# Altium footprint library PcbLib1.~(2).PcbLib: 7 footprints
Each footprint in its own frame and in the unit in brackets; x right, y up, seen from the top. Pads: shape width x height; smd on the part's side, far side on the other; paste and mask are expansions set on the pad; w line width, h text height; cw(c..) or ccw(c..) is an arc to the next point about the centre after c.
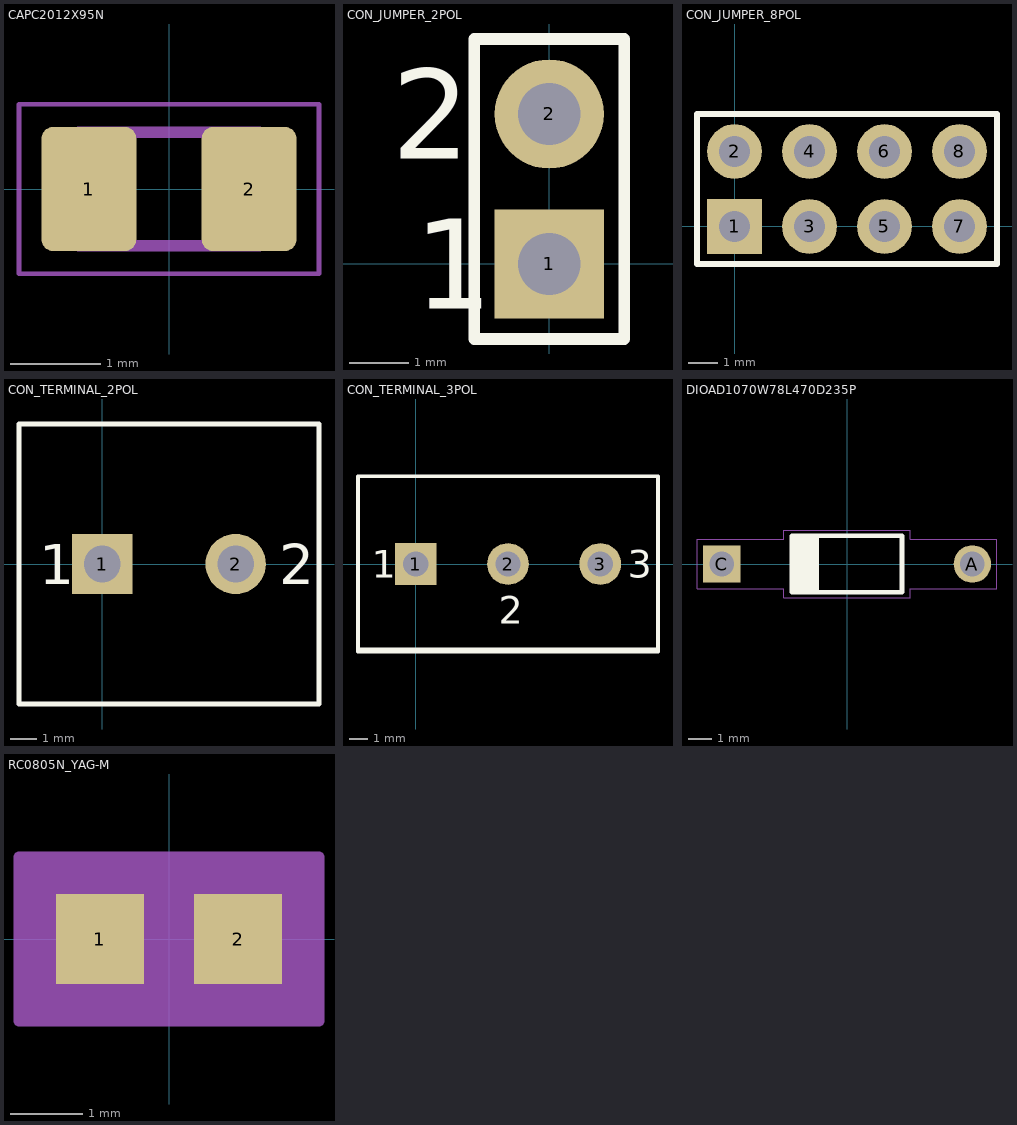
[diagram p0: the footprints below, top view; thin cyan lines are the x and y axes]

## CAPC2012X95N [mm]
pads (2):
  rrect25% 1.05x1.38 smd: 1(-0.888,0) 2(0.888,0)
Mechanical 13:
  lines w0.127: -1,-0.63 1,-0.63 1,0.63 -1,0.63 -1,-0.63
Mechanical 15:
  lines w0.05: -1.663,-0.94 1.663,-0.94 1.663,0.94 -1.663,0.94 -1.663,-0.94
3D body "step_temp.STEP": height 0.95, standoff 0, extent -1,-0.625 1,0.625

## CON_JUMPER_2POL [mm] "Jumper"
pads (2):
  rect 1.85x1.85 hole 1.05: 1(0,0)
  round 1.85 hole 1.05: 2(0,2.54)
Top Overlay:
  lines w0.2: -1.27,-1.27 -1.27,2.54 -1.27,3.81 1.27,3.81 1.27,-1.27 -1.27,-1.27
  text "2" at -2.667,1.778 h1.52
  text "1" at -2.286,-0.762 h1.52

## CON_JUMPER_8POL [mm] "Jumper"
pads (8):
  rect 1.85x1.85 hole 1.05: 1(0,0)
  round 1.85 hole 1.05: 2(0,2.54) 3(2.54,0) 4(2.54,2.54) 5(5.08,0) 6(5.08,2.54) 7(7.62,0) 8(7.62,2.54)
Top Overlay:
  lines w0.2: -1.27,-1.27 -1.27,3.81 8.89,3.81 8.89,-1.27 -1.27,-1.27

## CON_TERMINAL_2POL [mm] "Terminal Screw"
pads (2):
  rect 2.3x2.3 hole 1.4: 1(0,0)
  round 2.3 hole 1.4: 2(5.08,0)
Top Overlay:
  lines w0.2: -3.175,-5.334 8.255,-5.334 8.255,5.334 -3.175,5.334 -3.175,0 -3.175,-5.334
  text "1" at -2.413,-0.762 h1.52
  text "2" at 6.731,-0.762 h1.52

## CON_TERMINAL_3POL [mm] "Terminal Screw"
pads (3):
  rect 2.3x2.3 hole 1.4: 1(0,0)
  round 2.3 hole 1.4: 2(5.08,0) 3(10.16,0)
Top Overlay:
  lines w0.2: -3.048,-4.699 13.208,-4.699 ; -3.175,-4.826 -3.175,0 -3.175,4.826 13.335,4.826 13.335,-4.826 -3.175,-4.826
  text "3" at 11.684,-0.762 h1.52
  text "2" at 4.572,-3.302 h1.52
  text "1" at -2.413,-0.762 h1.52

## DIOAD1070W78L470D235P [mm]
pads (2):
  round 1.6 hole 1.05: A(5.35,0)
  rect 1.6x1.6 / inner round 1.6 / far side rect 1.6x1.6 hole 1.05: C(-5.35,0)
Top Overlay:
  region: -1.2,-1.202 -2.403,-1.202 -2.403,1.2 -1.2,1.2
  lines w0.2: -2.35,-1.2 2.35,-1.2 2.35,1.2 -2.35,1.2 -2.35,-1.2
Mechanical 15:
  lines w0.05: -6.4,-1.05 -2.7,-1.05 -2.7,-1.45 2.7,-1.45 2.7,-1.05 6.4,-1.05 6.4,1.05 2.7,1.05 2.7,1.45 -2.7,1.45 -2.7,1.05 -6.4,1.05 -6.4,-1.05
3D body "step_temp.STEP": height 2.7, standoff -21.05, extent -5.743,-1.35 5.743,1.35

## RC0805N_YAG-M [mil]
pads (2):
  rect 48x49 smd paste+0 mask+0: 1(-37.5,0) 2(37.5,0)
Mechanical 13:
  lines w1: -39.5,-23.5 -39.5,23.5 ; -39.5,-23.5 39.5,-23.5 ; -39.5,-23.5 -13.5,-23.5 -13.5,23.5 -39.5,23.5 ; -39.5,-23.5 -39.5,23.5 ; -39.5,23.5 39.5,23.5 ; 39.5,-23.5 39.5,23.5 ; 39.5,-23.5 39.5,23.5 ; 39.5,-23.5 13.5,-23.5 13.5,23.5 39.5,23.5
Mechanical 15:
  region: 81.5,-44.5 -81.5,-44.5 -81.5,44.5 81.5,44.5
  lines w6: -81.5,-44.5 81.5,-44.5 81.5,44.5 -81.5,44.5 -81.5,-44.5
3D body "RC0805N_YAG.step": height 27.99, standoff 0, extent -39.49,-23.5 39.49,23.5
